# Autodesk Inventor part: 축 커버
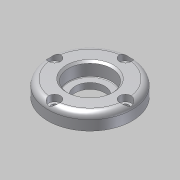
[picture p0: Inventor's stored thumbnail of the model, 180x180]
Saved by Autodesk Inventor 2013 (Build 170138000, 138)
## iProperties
Created: 2013-08
Part Number: 축 커버
Document SubType Name: Modeling
Designer: 한국산업디자인학원
Density: 1 g/cm^3
Material: 일반
Author: 한국산업디자인학원
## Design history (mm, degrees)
sketch "스케치1"
  geometry: C1 r 21.36 at (0, 0) reference; 1 further point
extrude "돌출1" new body sketch "스케치1" distance "d0" = 8; taper "d1" = 0 deg
sketch "스케치2"
  geometry: C1 r 14 at (0, 0) reference; 1 further point
extrude "돌출2" join sketch "스케치2" distance "d2" = 2; taper "d3" = 0 deg
sketch "스케치3"
  geometry: C1 r 1.23 at (0, 18) reference; 1 further point
hole "구멍1" sketch "스케치3" at (0, 18) diameter "d4" = 3.4; stored, may be unused: countersink angle "d8" = 90 deg, drill point angle "d10" = 118 deg; dims "d5" = 6, "d6" = 6, "d7" = 3.3, "d9" = 8
hole "구멍2" diameter "d16" = 15; stored, may be unused: countersink angle "d20" = 90 deg, drill point angle "d22" = 118 deg; dims "d14" = 10, "d15" = 10, "d17" = 6, "d18" = 22, "d19" = 7, "d21" = 8
fillet "모깎기1" dims "d23" = 3, "d24" = 0.3
chamfer "모따기1" distance "d25" = 1; stored, may be unused: second distance "d26" = 2, angle "d27" = 45 deg
node "솔리드1"
pattern_circular "원형 패턴1" dims angle "d12" = 360 deg
node "참조1"
node "참조2"
node "참조3"
